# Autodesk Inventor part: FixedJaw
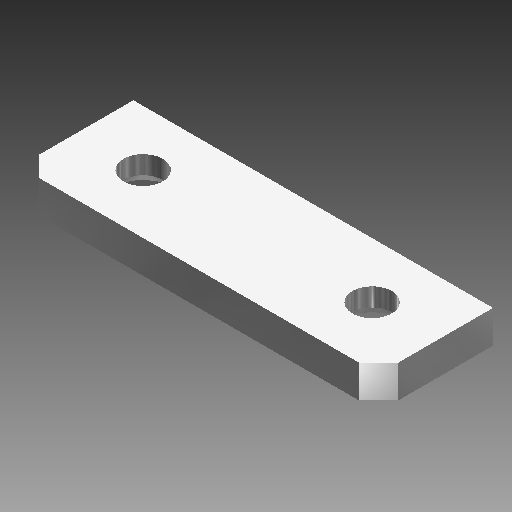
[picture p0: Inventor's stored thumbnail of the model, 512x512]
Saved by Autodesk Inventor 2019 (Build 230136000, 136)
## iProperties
Created: 2011-02
Part Number: FixedJaw
Material: Generic
Document SubType Name: Modeling
Designer: landrews
Density: 1 g/cm^3
Appearance: Chrome - Polished
Mass: 4.37122 g
Surface Area: 26.5384 cm^2
Volume: 4.37122 cm^3
Author: landrews
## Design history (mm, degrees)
sketch "Sketch1"
  geometry: L1 (-38.5, 0)-(38.5, 0) reference; L2 (27.5, 0)-(-27.5, 0); L3 (-27.5, 0)-(-27.5, -17.5); L4 (-27.5, -17.5)-(27.5, -17.5); L5 (27.5, -17.5)-(27.5, 0); L6 (0, -21)-(0, 3.5) reference
  constraints: 8 end point, 2 parallel, 1 horizontal, 1 perpendicular, 1 point on line, 1 other
  dimensions: "d8" = 17.5 distance between parallel lines of L4 L1; "d22" = 55 distance of L3.end L4.end
extrude "Extrusion1" new body sketch "Sketch1" distance "d5" = 5; taper "d6" = 0 deg
sketch "Sketch2"
  geometry: L1 (-27.5, 0)-(27.5, 0) reference; L2 (27.5, 0)-(27.5, -17.5) reference; L3 (-27.5, -17.5)-(-27.5, 0) reference; 2 further points
  constraints: 1 horizontal alignment
  dimensions: "d9" = 9 distance from line of L1 point (17.5, -9); "d23" = 10 distance from line of L3 point (-17.5, -9); "d24" = 10 distance from line of L2 point (17.5, -9) (= d23)
hole "Hole1" sketch "Sketch2" at (17.5, -9), (-17.5, -9) diameter "d12" = 6; stored, may be unused: countersink angle "d16" = 90 deg, drill point angle "d18" = 118 deg; dims "d13" = 6, "d14" = 10.4, "d15" = 2, "d17" = 8
chamfer "Chamfer1" distance "d19" = 3; stored, may be unused: second distance "d20" = 2, angle "d21" = 45 deg
body "Solid1"
